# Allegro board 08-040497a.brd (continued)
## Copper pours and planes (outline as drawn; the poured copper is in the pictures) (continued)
AGND on TOP (solid shape): 46,36.25 45.88,36.12 42.75,36.12 42.62,36.25 42.62,39.62 46,39.62
AGND on TOP (solid shape): 46.12,60.5 46,60.38 42.88,60.38 42.75,60.5 42.75,63.88 46.12,63.88
AGND on TOP (solid shape): 53.12,49.42 51.73,49.42 51.73,49.78 52.25,49.78 52.25,50.72 51.73,50.72 51.73,51.08 53.12,51.08
AGND on BOTTOM (solid shape): 9.62,61.25 9.62,58 9.12,57.5 6.12,57.5 6,57.62 6,61.38 9.5,61.38
AGND on BOTTOM (solid shape): 9.62,42.25 9.62,39 9.12,38.5 6.12,38.5 6,38.62 6,42.38 9.5,42.38
AGND on BOTTOM (solid shape): 19,61.25 19,58 18.5,57.5 15.5,57.5 15.38,57.62 15.38,61.38 18.88,61.38
AGND on BOTTOM (solid shape): 19.12,42.38 19.12,39.12 18.62,38.62 15.62,38.62 15.5,38.75 15.5,42.5 19,42.5
AGND on BOTTOM (solid shape): 36.88,39.62 36.88,36.38 36.38,35.88 33.38,35.88 33.25,36 33.25,39.75 36.75,39.75
AGND on BOTTOM (solid shape): 37,64.12 37,60.88 36.5,60.38 33.5,60.38 33.38,60.5 33.38,64.25 36.88,64.25
AGND on BOTTOM (solid shape): 46.12,64 46.12,60.75 45.62,60.25 42.62,60.25 42.5,60.38 42.5,64.12 46,64.12
AGND on BOTTOM (solid shape): 46.38,39.5 46.38,36.25 45.88,35.75 42.88,35.75 42.75,35.88 42.75,39.62 46.25,39.62
AGND on TOP: 137.75,77 133.25,77 132.75,76.5 132.75,70.75 132.25,70.25 132,70.25 132,64.75 142,64.75 142,67.5 141.25,68.25 141.25,69.75 142.25,70.75 146.25,70.75 146.25,71.75 141.25,71.75 139.75,70.25 139.75,69.5 139.25,69 136.25,69 134.75,70.5 134.75,75 135,75.25 137.75,75.25
AGND on TOP: 149.5,91.5 143.25,91.5 142.75,91 142.75,85.75 141.5,85.75 141.5,85.25 142.75,85.25 142.75,83.75 142.5,83.5 141.75,83.5 141.75,79.5 145,79.5 145.25,79.75 145.25,83.25 144.25,84.25 144.25,86.5 145.25,87.5 145.25,89.5 145.75,90 147.25,90 148,89.25 149.5,89.25
AGND on TOP, BOTTOM, L2-GND, L3-GND: 199.5,99.5 70.5,99.5 70.5,64.5 47.5,64.5 47.5,65 32,65 32,64.5 25.5,64.5 25.5,61.75 20.5,61.75 20.5,62.25 4.25,62.25 4.25,61.75 0.5,61.75 0.5,38.25 4.5,38.25 4.5,37.75 20.75,37.75 20.75,38.25 25.5,38.25 25.5,35.5 31.75,35.5 31.75,35 47.75,35 47.75,35.5 70.5,35.5 70.5,0.5 199.5,0.5
AVDD on TOP: 142,69.75 143.75,69.75 144,70 146.5,70 146.5,61.5 144.75,61.5 144,62.25 102.75,62.25 98.25,57.75 98.25,51 97,51 96.75,51.25 96.75,57.5 95.75,58.5 95.75,61.25 98.75,64.25 142.25,64.25 142.75,64.75 142.75,67.75 142,68.5
UNNAMED_4_ADM660_I4_OUT on TOP: 147,57 151.25,57 151.25,54.25 147,54.25
UNNAMED_4_ADM660_I4_V on TOP: 147,63.5 147,60 149.5,60 149.5,63.5
UNNAMED_4_ADM7170_I67_EN on TOP: 134.5,87.75 136.75,87.75 138,86.5 142.25,86.5 142.25,86 134.75,86 134.5,86.25
UNNAMED_4_ADM7170_I67_SENSE on TOP: 144.75,85.75 145.75,85.75 147.75,87.75 147.75,88.5 149.75,88.5 150.5,89.25 152,89.25 152,84.25 151.75,84 150.5,84 149.25,85.25 144.75,85.25
UNNAMED_4_ADM7170_I67_SS on TOP: 147.25,89.5 146,89.5 145.75,89.25 145.75,87.25 145.5,87 145.25,87 144.5,86.25 144.5,86 145.5,86 147.25,87.75
UNNAMED_4_ADM7170_I67_VOUT1 on TOP: 144.75,85 147.5,85 147.75,84.75 149.25,84.75 150.5,83.5 152.5,83.5 153.5,84.5 155.25,84.5 155.25,81.5 149.25,81.5 148.75,81 146,81 145.75,81.25 145.75,83.25 144.75,84.25
UNNAMED_4_ADP2301_I57_BST on TOP: 176,89.75 174.5,89.75 174.5,87 176,87
UNNAMED_4_ADP2301_I57_EN on TOP: 162.75,89 161,89 161,84 162.75,84
UNNAMED_4_ADP2301_I57_FB on TOP: 174.75,92.75 174.75,91.25 176.25,91.25 177,90.5 178.75,90.5 179.25,91 181,91 181,92.75
UNNAMED_4_ADP2301_I57_SW on TOP: 172,90 172,85 171.5,84.5 169.25,84.5 169.25,81.75 174.5,81.75 174.5,85.75 173.75,86.5 173.75,88.5 173.25,89 173.25,90
UNNAMED_4_ADP3303_I47_NR on TOP: 135.25,74.75 139.25,74.75 139.25,74 135.25,74
UNNAMED_4_ADP3303_I47_OUT on TOP: 135.25,73.5 139.75,73.5 140,73.75 141.25,73.75 141.25,72.25 140,71 135.25,71
UNNAMED_4_CAP_I91_N2 on TOP: 155.25,89.25 152.75,89.25 152.5,89 152.5,85.5 152.75,85.25 155,85.25 155.25,85.5
UNNAMED_4_CN2P_I42_N1 on TOP: 124.5,97 119.75,97 118,95.25 118,69.75 118.25,69.5 121.75,69.5 125,72.75 125,96.5
UNNAMED_4_CN4PV2_I45_N3 on TOP: 98,97 102.5,97 103.5,96 103.5,75.75 106.25,73 113.75,73 114.25,72.5 114.25,69.75 114,69.5 101.25,69.5 97.75,73 97.75,96.75
V_IN on TOP: 115,72.75 117,72.75 117.25,72.5 117.25,69.25 117.75,68.75 122.25,68.75 126.25,72.75 126.25,87 134.25,95 167.25,95 171.5,90.75 173.25,90.75 173.25,90.5 173,90.25 171.5,90.25 170.75,89.5 169.25,89.5 168.75,89 166,89 163,92 137.25,92 133.5,88.25 133.5,86 134.5,85 142.25,85 142.25,84 141.5,84 141,83.5 141,80.75 139.75,79.5 132.25,79.5 131.75,79 131.75,75.5 129.25,75.5 129.25,73.5 129.5,73.25 132.25,73.25 132.25,71.5 131.75,71 131.5,71 131.25,70.75 131.25,66.5 130,65.25 115.75,65.25 115,66
VDET on TOP: 148,69.5 152.75,69.5 152.75,64.25 148,64.25
VDET on TOP: 155.25,81 152.5,81 152.5,77 152.75,76.75 155,76.75 155.25,77
VDET on TOP: 59.75,59.5 56.5,59.5 53.25,56.25 53.25,51.75 53.5,51.5 53.5,50.75 54.5,50.75 59.75,56
VDET on BOTTOM: 148.25,67 80.25,67 72.75,59.5 56,59.5 56,56.5 57,55.5 75.5,55.5 84.25,64.25 148.75,64.25 148.75,66.5
VDET on BOTTOM: 152.25,80.25 152.25,71.25 148,67 148,64.5 148.25,64.25 152.75,64.25 156.25,67.75 156.25,80.25
VDRIVE on TOP: 164.75,47.25 142.5,47.25 129,60.75 115.75,60.75 107.5,52.5 101.75,52.5 101.75,51 110,51 117,58 127,58 141,44 164.5,44 164.75,44.25
VIO_CONNECTOR on TOP: 167,47.25 168,48.25 184.75,48.25 189,44 191.5,44 191.5,43.5 189,43.5 188.5,43 169.25,43 167,45.25
VNEG on TOP: 147,53.5 147,48.25 153.25,48.25 153.5,48.5 153.5,53.5
VNEG on TOP: 99.75,28 120.25,28 121,27.25 121,12.75 119.25,11 99.75,11 99.75,13.5 116.75,13.5 117.75,14.5 117.75,24.75 116.75,25.75 105.5,25.75 103.75,24 100.5,24 100.5,24.5 99.75,25.25
VNEG on BOTTOM: 151.75,51.75 142.5,51.75 116.38,25.62 119.5,22.5 120.75,22.5 146.5,48.25 151.75,48.25
VSDP on TOP: 177,90 177,62.25 193.25,46 197.5,46 197.5,47.25 194.5,47.25 184.25,57.5 184.25,84 184,84.25 180.75,84.25 178.75,86.25 178.75,90
VSDP_EN on TOP: 163.25,83.5 161,83.5 160.75,83.25 160.75,77.5 158.25,75 142.75,75 142,74.25 142,72.5 142.25,72.25 147.75,72.25 148.75,71.25 159.5,71.25 163.5,75.25 163.5,83.25

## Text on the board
Ref Des/Silkscreen Top: EV-VSWR-SDZ | 08-040497 Rev-A
DIMENSION: Note the 8x half-moon holes at board edge. | These are plated and connected to the GND plane on all 4 layers. | SEE NOTE 13 | 16   NOTE THE SIX HOLES AT THE EDGE OF THE BOARD THAT WILL BE A HALF MOON AND PLATED. | 15.    FINISHED BOARD MUST BE ROHS & REACH COMLPIANT. | FR4 CORE
User.17: L02-GROUND PLANE | 08-      -08
User.18: L03 - GROUND PLANE | 08-      -09
User.45: FIGURE | SIZE | 0.254 | 0.4064 | 0.9906 | 1.016 | 1.143 | 1.397 | 1.6002 | 1.905 | 2.1082 | 0.7112 | 1.0922 | 1.8034 | 3.175 | DRILL CHART: TOP to BOTTOM | ALL UNITS ARE IN MILLIMETERS | PLATED | NON-PLATED | QTY | 1764 | 55 | 8 | 2 | 3 | 4 | 16 | 1
